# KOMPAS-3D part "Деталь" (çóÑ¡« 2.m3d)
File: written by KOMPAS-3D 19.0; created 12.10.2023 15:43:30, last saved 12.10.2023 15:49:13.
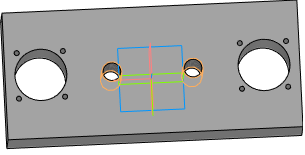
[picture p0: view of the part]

Document properties: Автор: admin; Организация: Hewlett-Packard Company; Полное имя файла: C:\Users\Petrenko-VE\Documents\Звено_2.m3d

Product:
- Part/product: Деталь
    Масса: 7.88056

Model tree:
1. Эскиз:1
2. Элемент выдавливания:1
     Расстояние 1 = 50
3. Эскиз:2  (with: Элемент выдавливания:1)
4. Элемент выдавливания:2
     Расстояние 2 = 50
5. Эскиз:3  (with: Элемент выдавливания:1)
6. Элемент выдавливания:3
     Расстояние 2 = 50
7. Условное изображение резьбы:1  (with: Элемент выдавливания:3)  (labels: M16; cil0_24705-2004 coarse)
     Длина резьбы = 50; Шаг резьбы = 2; Номинальный диаметр резьбы = 16
8. Подгонка:1  (with: Элемент выдавливания:3)
9. Условное изображение резьбы:2  (with: Элемент выдавливания:3)  (labels: M16; cil0_24705-2004 coarse)
     Длина резьбы = 50; Шаг резьбы = 2; Номинальный диаметр резьбы = 16
10. Подгонка:2  (with: Элемент выдавливания:3)
11. Эскиз:4  (with: Элемент выдавливания:1, Элемент выдавливания:2)
12. Элемент выдавливания:4
     Расстояние 2 = 30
